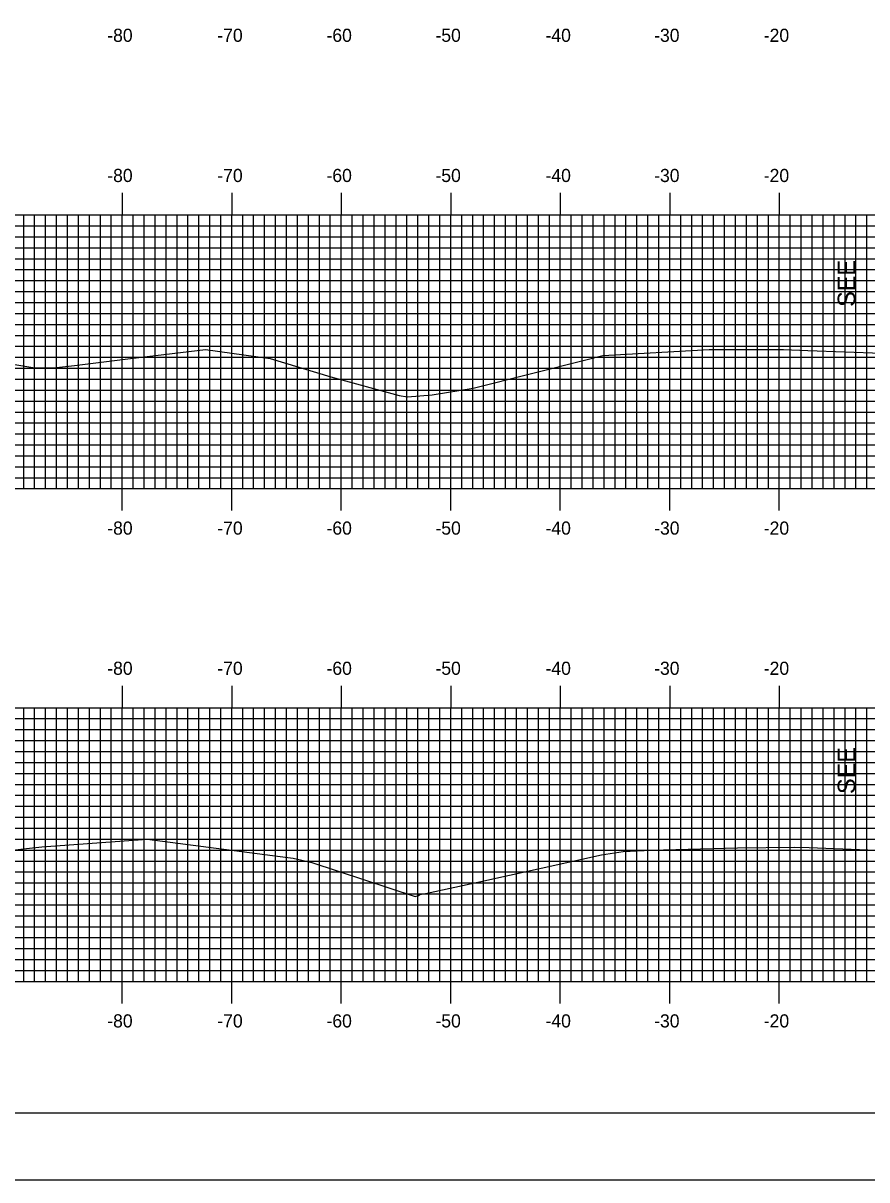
# Model space of a CAD drawing. Extents: x 1685979 to 1686323, y 461260 to 461480.
# Drawn here: x 1686056.2 to 1686133.3, y 461260 to 461365.6 of the extents above; entities that cross this region are included whole.
import ezdxf

# ---------------------------------------------------------------- set-up
doc = ezdxf.new("R2010")
doc.units = 0
for name, color, linetype in [('ANNOTATION', 7, 'Continuous'), ('BORDER', 7, 'Continuous'), ('D_Roadway_Centerline', 7, 'Continuous'), ('H_V ANNOTATION', 7, 'Continuous'), ('M_Roadway_Centerline', 7, 'Continuous'), ('MAJOR', 7, 'Continuous'), ('MINOR', 7, 'Continuous'), ('PLOT BOUNDARY', 7, 'Continuous'), ('S_Roadway_Centerline', 7, 'Continuous')]:
    doc.layers.add(name, color=color, linetype=linetype)

msp = doc.modelspace()

# ---------------------------------------------------------------- linework, layer by layer
at = {"layer": 'BORDER'}
msp.add_lwpolyline([(1685995.66, 461266.07), (1686315.66, 461266.07), (1686315.66, 461476.07), (1685995.66, 461476.07)], close=True, dxfattribs=at)
at = {"layer": 'MAJOR'}
for p, q in [((1686065.26, 461350.08), (1686065.26, 461348.07)), ((1686075.26, 461350.08), (1686075.26, 461348.07)), ((1686085.26, 461350.08), (1686085.26, 461348.07)), ((1686095.26, 461350.08), (1686095.26, 461348.07)), ((1686105.26, 461350.08), (1686105.26, 461348.07)), ((1686115.26, 461350.08), (1686115.26, 461348.07)), ((1686125.26, 461350.08), (1686125.26, 461348.07)), ((1686005.26, 461348.07), (1686285.26, 461348.07)), ((1686005.26, 461348.07), (1686285.26, 461348.07)), ((1686065.26, 461323.07), (1686065.26, 461348.07)), ((1686075.26, 461323.07), (1686075.26, 461348.07)), ((1686085.26, 461323.07), (1686085.26, 461348.07)), ((1686095.26, 461323.07), (1686095.26, 461348.07)), ((1686105.26, 461323.07), (1686105.26, 461348.07)), ((1686115.26, 461323.07), (1686115.26, 461348.07)), ((1686125.26, 461323.07), (1686125.26, 461348.07)), ((1686005.26, 461343.07), (1686285.26, 461343.07)), ((1686005.26, 461338.07), (1686285.26, 461338.07)), ((1686005.26, 461333.07), (1686285.26, 461333.07)), ((1686005.26, 461328.07), (1686285.26, 461328.07)), ((1686005.26, 461323.07), (1686285.26, 461323.07)), ((1686005.26, 461323.07), (1686285.26, 461323.07)), ((1686065.26, 461321.07), (1686065.26, 461323.07)), ((1686075.26, 461321.07), (1686075.26, 461323.07)), ((1686085.26, 461321.07), (1686085.26, 461323.07)), ((1686095.26, 461321.07), (1686095.26, 461323.07)), ((1686105.26, 461321.07), (1686105.26, 461323.07)), ((1686115.26, 461321.07), (1686115.26, 461323.07)), ((1686125.26, 461321.07), (1686125.26, 461323.07)), ((1686065.26, 461305.08), (1686065.26, 461303.07)), ((1686075.26, 461305.08), (1686075.26, 461303.07)), ((1686085.26, 461305.08), (1686085.26, 461303.07)), ((1686095.26, 461305.08), (1686095.26, 461303.07)), ((1686105.26, 461305.08), (1686105.26, 461303.07)), ((1686115.26, 461305.08), (1686115.26, 461303.07)), ((1686125.26, 461305.08), (1686125.26, 461303.07)), ((1686005.26, 461303.07), (1686285.26, 461303.07)), ((1686005.26, 461303.07), (1686285.26, 461303.07)), ((1686065.26, 461278.07), (1686065.26, 461303.07)), ((1686075.26, 461278.07), (1686075.26, 461303.07)), ((1686085.26, 461278.07), (1686085.26, 461303.07)), ((1686095.26, 461278.07), (1686095.26, 461303.07)), ((1686105.26, 461278.07), (1686105.26, 461303.07)), ((1686115.26, 461278.07), (1686115.26, 461303.07)), ((1686125.26, 461278.07), (1686125.26, 461303.07)), ((1686005.26, 461298.07), (1686285.26, 461298.07)), ((1686005.26, 461293.07), (1686285.26, 461293.07)), ((1686005.26, 461288.07), (1686285.26, 461288.07)), ((1686005.26, 461283.07), (1686285.26, 461283.07)), ((1686005.26, 461278.07), (1686285.26, 461278.07)), ((1686005.26, 461278.07), (1686285.26, 461278.07)), ((1686065.26, 461276.07), (1686065.26, 461278.07)), ((1686075.26, 461276.07), (1686075.26, 461278.07)), ((1686085.26, 461276.07), (1686085.26, 461278.07)), ((1686095.26, 461276.07), (1686095.26, 461278.07)), ((1686105.26, 461276.07), (1686105.26, 461278.07)), ((1686115.26, 461276.07), (1686115.26, 461278.07)), ((1686125.26, 461276.07), (1686125.26, 461278.07))]:
    msp.add_line(p, q, dxfattribs=at)
at = {"layer": 'MINOR'}
for p, q in [((1686056.26, 461323.07), (1686056.26, 461348.07)), ((1686057.26, 461323.07), (1686057.26, 461348.07)), ((1686058.26, 461323.07), (1686058.26, 461348.07)), ((1686059.26, 461323.07), (1686059.26, 461348.07)), ((1686060.26, 461323.07), (1686060.26, 461348.07)), ((1686061.26, 461323.07), (1686061.26, 461348.07)), ((1686062.26, 461323.07), (1686062.26, 461348.07)), ((1686063.26, 461323.07), (1686063.26, 461348.07)), ((1686064.26, 461323.07), (1686064.26, 461348.07)), ((1686066.26, 461323.07), (1686066.26, 461348.07)), ((1686067.26, 461323.07), (1686067.26, 461348.07)), ((1686068.26, 461323.07), (1686068.26, 461348.07)), ((1686069.26, 461323.07), (1686069.26, 461348.07)), ((1686070.26, 461323.07), (1686070.26, 461348.07)), ((1686071.26, 461323.07), (1686071.26, 461348.07)), ((1686072.26, 461323.07), (1686072.26, 461348.07)), ((1686073.26, 461323.07), (1686073.26, 461348.07)), ((1686074.26, 461323.07), (1686074.26, 461348.07)), ((1686076.26, 461323.07), (1686076.26, 461348.07)), ((1686077.26, 461323.07), (1686077.26, 461348.07)), ((1686078.26, 461323.07), (1686078.26, 461348.07)), ((1686079.26, 461323.07), (1686079.26, 461348.07)), ((1686080.26, 461323.07), (1686080.26, 461348.07)), ((1686081.26, 461323.07), (1686081.26, 461348.07)), ((1686082.26, 461323.07), (1686082.26, 461348.07)), ((1686083.26, 461323.07), (1686083.26, 461348.07)), ((1686084.26, 461323.07), (1686084.26, 461348.07)), ((1686086.26, 461323.07), (1686086.26, 461348.07)), ((1686087.26, 461323.07), (1686087.26, 461348.07)), ((1686088.26, 461323.07), (1686088.26, 461348.07)), ((1686089.26, 461323.07), (1686089.26, 461348.07)), ((1686090.26, 461323.07), (1686090.26, 461348.07)), ((1686091.26, 461323.07), (1686091.26, 461348.07)), ((1686092.26, 461323.07), (1686092.26, 461348.07)), ((1686093.26, 461323.07), (1686093.26, 461348.07)), ((1686094.26, 461323.07), (1686094.26, 461348.07)), ((1686096.26, 461323.07), (1686096.26, 461348.07)), ((1686097.26, 461323.07), (1686097.26, 461348.07)), ((1686098.26, 461323.07), (1686098.26, 461348.07)), ((1686099.26, 461323.07), (1686099.26, 461348.07)), ((1686100.26, 461323.07), (1686100.26, 461348.07)), ((1686101.26, 461323.07), (1686101.26, 461348.07)), ((1686102.26, 461323.07), (1686102.26, 461348.07)), ((1686103.26, 461323.07), (1686103.26, 461348.07)), ((1686104.26, 461323.07), (1686104.26, 461348.07)), ((1686106.26, 461323.07), (1686106.26, 461348.07)), ((1686107.26, 461323.07), (1686107.26, 461348.07)), ((1686108.26, 461323.07), (1686108.26, 461348.07)), ((1686109.26, 461323.07), (1686109.26, 461348.07)), ((1686110.26, 461323.07), (1686110.26, 461348.07)), ((1686111.26, 461323.07), (1686111.26, 461348.07)), ((1686112.26, 461323.07), (1686112.26, 461348.07)), ((1686113.26, 461323.07), (1686113.26, 461348.07)), ((1686114.26, 461323.07), (1686114.26, 461348.07)), ((1686116.26, 461323.07), (1686116.26, 461348.07)), ((1686117.26, 461323.07), (1686117.26, 461348.07)), ((1686118.26, 461323.07), (1686118.26, 461348.07)), ((1686119.26, 461323.07), (1686119.26, 461348.07)), ((1686120.26, 461323.07), (1686120.26, 461348.07)), ((1686121.26, 461323.07), (1686121.26, 461348.07)), ((1686122.26, 461323.07), (1686122.26, 461348.07)), ((1686123.26, 461323.07), (1686123.26, 461348.07)), ((1686124.26, 461323.07), (1686124.26, 461348.07)), ((1686126.26, 461323.07), (1686126.26, 461348.07)), ((1686127.26, 461323.07), (1686127.26, 461348.07)), ((1686128.26, 461323.07), (1686128.26, 461348.07)), ((1686129.26, 461323.07), (1686129.26, 461348.07)), ((1686130.26, 461323.07), (1686130.26, 461348.07)), ((1686131.26, 461323.07), (1686131.26, 461348.07)), ((1686132.26, 461323.07), (1686132.26, 461348.07)), ((1686133.26, 461323.07), (1686133.26, 461348.07)), ((1686005.26, 461347.07), (1686285.26, 461347.07)), ((1686005.26, 461346.07), (1686285.26, 461346.07)), ((1686005.26, 461345.07), (1686285.26, 461345.07)), ((1686005.26, 461344.07), (1686285.26, 461344.07)), ((1686005.26, 461342.07), (1686285.26, 461342.07)), ((1686005.26, 461341.07), (1686285.26, 461341.07)), ((1686005.26, 461340.07), (1686285.26, 461340.07)), ((1686005.26, 461339.07), (1686285.26, 461339.07)), ((1686005.26, 461337.07), (1686285.26, 461337.07)), ((1686005.26, 461336.07), (1686285.26, 461336.07)), ((1686005.26, 461335.07), (1686285.26, 461335.07)), ((1686005.26, 461334.07), (1686285.26, 461334.07)), ((1686005.26, 461332.07), (1686285.26, 461332.07)), ((1686005.26, 461331.07), (1686285.26, 461331.07)), ((1686005.26, 461330.07), (1686285.26, 461330.07)), ((1686005.26, 461329.07), (1686285.26, 461329.07)), ((1686005.26, 461327.07), (1686285.26, 461327.07)), ((1686005.26, 461326.07), (1686285.26, 461326.07)), ((1686005.26, 461325.07), (1686285.26, 461325.07)), ((1686005.26, 461324.07), (1686285.26, 461324.07)), ((1686056.26, 461278.07), (1686056.26, 461303.07)), ((1686057.26, 461278.07), (1686057.26, 461303.07)), ((1686058.26, 461278.07), (1686058.26, 461303.07)), ((1686059.26, 461278.07), (1686059.26, 461303.07)), ((1686060.26, 461278.07), (1686060.26, 461303.07)), ((1686061.26, 461278.07), (1686061.26, 461303.07)), ((1686062.26, 461278.07), (1686062.26, 461303.07)), ((1686063.26, 461278.07), (1686063.26, 461303.07)), ((1686064.26, 461278.07), (1686064.26, 461303.07)), ((1686066.26, 461278.07), (1686066.26, 461303.07)), ((1686067.26, 461278.07), (1686067.26, 461303.07)), ((1686068.26, 461278.07), (1686068.26, 461303.07)), ((1686069.26, 461278.07), (1686069.26, 461303.07)), ((1686070.26, 461278.07), (1686070.26, 461303.07)), ((1686071.26, 461278.07), (1686071.26, 461303.07)), ((1686072.26, 461278.07), (1686072.26, 461303.07)), ((1686073.26, 461278.07), (1686073.26, 461303.07)), ((1686074.26, 461278.07), (1686074.26, 461303.07)), ((1686076.26, 461278.07), (1686076.26, 461303.07)), ((1686077.26, 461278.07), (1686077.26, 461303.07)), ((1686078.26, 461278.07), (1686078.26, 461303.07)), ((1686079.26, 461278.07), (1686079.26, 461303.07)), ((1686080.26, 461278.07), (1686080.26, 461303.07)), ((1686081.26, 461278.07), (1686081.26, 461303.07)), ((1686082.26, 461278.07), (1686082.26, 461303.07)), ((1686083.26, 461278.07), (1686083.26, 461303.07)), ((1686084.26, 461278.07), (1686084.26, 461303.07)), ((1686086.26, 461278.07), (1686086.26, 461303.07)), ((1686087.26, 461278.07), (1686087.26, 461303.07)), ((1686088.26, 461278.07), (1686088.26, 461303.07)), ((1686089.26, 461278.07), (1686089.26, 461303.07)), ((1686090.26, 461278.07), (1686090.26, 461303.07)), ((1686091.26, 461278.07), (1686091.26, 461303.07)), ((1686092.26, 461278.07), (1686092.26, 461303.07)), ((1686093.26, 461278.07), (1686093.26, 461303.07)), ((1686094.26, 461278.07), (1686094.26, 461303.07)), ((1686096.26, 461278.07), (1686096.26, 461303.07)), ((1686097.26, 461278.07), (1686097.26, 461303.07)), ((1686098.26, 461278.07), (1686098.26, 461303.07)), ((1686099.26, 461278.07), (1686099.26, 461303.07)), ((1686100.26, 461278.07), (1686100.26, 461303.07)), ((1686101.26, 461278.07), (1686101.26, 461303.07)), ((1686102.26, 461278.07), (1686102.26, 461303.07)), ((1686103.26, 461278.07), (1686103.26, 461303.07)), ((1686104.26, 461278.07), (1686104.26, 461303.07)), ((1686106.26, 461278.07), (1686106.26, 461303.07)), ((1686107.26, 461278.07), (1686107.26, 461303.07)), ((1686108.26, 461278.07), (1686108.26, 461303.07)), ((1686109.26, 461278.07), (1686109.26, 461303.07)), ((1686110.26, 461278.07), (1686110.26, 461303.07)), ((1686111.26, 461278.07), (1686111.26, 461303.07)), ((1686112.26, 461278.07), (1686112.26, 461303.07)), ((1686113.26, 461278.07), (1686113.26, 461303.07)), ((1686114.26, 461278.07), (1686114.26, 461303.07)), ((1686116.26, 461278.07), (1686116.26, 461303.07)), ((1686117.26, 461278.07), (1686117.26, 461303.07)), ((1686118.26, 461278.07), (1686118.26, 461303.07)), ((1686119.26, 461278.07), (1686119.26, 461303.07)), ((1686120.26, 461278.07), (1686120.26, 461303.07)), ((1686121.26, 461278.07), (1686121.26, 461303.07)), ((1686122.26, 461278.07), (1686122.26, 461303.07)), ((1686123.26, 461278.07), (1686123.26, 461303.07)), ((1686124.26, 461278.07), (1686124.26, 461303.07)), ((1686126.26, 461278.07), (1686126.26, 461303.07)), ((1686127.26, 461278.07), (1686127.26, 461303.07)), ((1686128.26, 461278.07), (1686128.26, 461303.07)), ((1686129.26, 461278.07), (1686129.26, 461303.07)), ((1686130.26, 461278.07), (1686130.26, 461303.07)), ((1686131.26, 461278.07), (1686131.26, 461303.07)), ((1686132.26, 461278.07), (1686132.26, 461303.07)), ((1686133.26, 461278.07), (1686133.26, 461303.07)), ((1686005.26, 461302.07), (1686285.26, 461302.07)), ((1686005.26, 461301.07), (1686285.26, 461301.07)), ((1686005.26, 461300.07), (1686285.26, 461300.07)), ((1686005.26, 461299.07), (1686285.26, 461299.07)), ((1686005.26, 461297.07), (1686285.26, 461297.07)), ((1686005.26, 461296.07), (1686285.26, 461296.07)), ((1686005.26, 461295.07), (1686285.26, 461295.07)), ((1686005.26, 461294.07), (1686285.26, 461294.07)), ((1686005.26, 461292.07), (1686285.26, 461292.07)), ((1686005.26, 461291.07), (1686285.26, 461291.07)), ((1686005.26, 461290.07), (1686285.26, 461290.07)), ((1686005.26, 461289.07), (1686285.26, 461289.07)), ((1686005.26, 461287.07), (1686285.26, 461287.07)), ((1686005.26, 461286.07), (1686285.26, 461286.07)), ((1686005.26, 461285.07), (1686285.26, 461285.07)), ((1686005.26, 461284.07), (1686285.26, 461284.07)), ((1686005.26, 461282.07), (1686285.26, 461282.07)), ((1686005.26, 461281.07), (1686285.26, 461281.07)), ((1686005.26, 461280.07), (1686285.26, 461280.07)), ((1686005.26, 461279.07), (1686285.26, 461279.07))]:
    msp.add_line(p, q, dxfattribs=at)
at = {"layer": 'PLOT BOUNDARY'}
msp.add_lwpolyline([(1685979.47, 461259.95), (1686319.47, 461259.95), (1686319.47, 461479.95), (1685979.47, 461479.95)], close=True, dxfattribs=at)
at = {"layer": 'S_Roadway_Centerline'}
for points in [[(1686055.28, 461334.45), (1686057.29, 461334.09), (1686058.99, 461334.11), (1686060.89, 461334.31), (1686066.02, 461334.95), (1686072.86, 461335.77), (1686078.77, 461334.97), (1686084.32, 461333.29), (1686090.54, 461331.58), (1686091.3, 461331.45), (1686093.57, 461331.63), (1686097.31, 461332.26), (1686107.72, 461334.86), (1686109.16, 461335.23), (1686118.87, 461335.79), (1686124.49, 461335.78), (1686125.57, 461335.77), (1686125.64, 461335.77), (1686127.87, 461335.69), (1686137.99, 461335.33)], [(1686045.06, 461288.85), (1686056.53, 461290.21), (1686057.93, 461290.36), (1686067.54, 461291.06), (1686080.38, 461289.39), (1686080.87, 461289.34), (1686082.57, 461288.92), (1686092.02, 461285.84), (1686092.32, 461285.92), (1686092.43, 461286.02), (1686093.11, 461286.12), (1686097.73, 461287.15), (1686109.02, 461289.62), (1686111.01, 461289.93), (1686113.55, 461290.06), (1686121.45, 461290.27), (1686126.66, 461290.34), (1686127.98, 461290.3), (1686135.67, 461290.01)]]:
    msp.add_lwpolyline(points, dxfattribs=at)

# ---------------------------------------------------------------- texts
at = {"layer": 'ANNOTATION'}
for p in [(1686132.19, 461339.67), (1686132.19, 461295.19)]:
    msp.add_text('SEE', height=1.6, rotation=90, dxfattribs=at).set_placement(p)
at = {"layer": 'D_Roadway_Centerline'}
for s, p in [('C', (1686112.88, 461335.09)), ('L', (1686112.89, 461335.08)), ('C', (1686107.52, 461289.79)), ('L', (1686107.52, 461289.78))]:
    msp.add_text(s, height=0.0146, dxfattribs=at).set_placement(p)
at = {"layer": 'H_V ANNOTATION'}
for s, p in [('-80', (1686063.89, 461363.87)), ('-70', (1686073.94, 461363.87)), ('-60', (1686083.91, 461363.87)), ('-50', (1686093.86, 461363.87)), ('-40', (1686103.91, 461363.87)), ('-30', (1686113.83, 461363.87)), ('-20', (1686123.84, 461363.87)), ('-80', (1686063.89, 461351.07)), ('-70', (1686073.94, 461351.07)), ('-60', (1686083.91, 461351.07)), ('-50', (1686093.86, 461351.07)), ('-40', (1686103.91, 461351.07)), ('-30', (1686113.83, 461351.07)), ('-20', (1686123.84, 461351.07)), ('-80', (1686063.89, 461318.87)), ('-70', (1686073.94, 461318.87)), ('-60', (1686083.91, 461318.87)), ('-50', (1686093.86, 461318.87)), ('-40', (1686103.91, 461318.87)), ('-30', (1686113.83, 461318.87)), ('-20', (1686123.84, 461318.87)), ('-80', (1686063.89, 461306.07)), ('-70', (1686073.94, 461306.07)), ('-60', (1686083.91, 461306.07)), ('-50', (1686093.86, 461306.07)), ('-40', (1686103.91, 461306.07)), ('-30', (1686113.83, 461306.07)), ('-20', (1686123.84, 461306.07)), ('-80', (1686063.89, 461273.87)), ('-70', (1686073.94, 461273.87)), ('-60', (1686083.91, 461273.87)), ('-50', (1686093.86, 461273.87)), ('-40', (1686103.91, 461273.87)), ('-30', (1686113.83, 461273.87)), ('-20', (1686123.84, 461273.87))]:
    msp.add_text(s, height=1.2, dxfattribs=at).set_placement(p)
at = {"layer": 'M_Roadway_Centerline'}
for s, p in [('C', (1686125.57, 461335.77)), ('L', (1686125.57, 461335.76)), ('C', (1686127.98, 461290.3)), ('L', (1686127.98, 461290.29))]:
    msp.add_text(s, height=0.0146, dxfattribs=at).set_placement(p)

doc.saveas('drawing.dxf')
